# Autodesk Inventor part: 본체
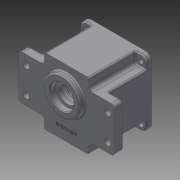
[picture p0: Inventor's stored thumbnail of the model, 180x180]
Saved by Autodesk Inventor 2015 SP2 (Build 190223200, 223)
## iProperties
Created: 2015-06
Part Number: 본체
Material: 일반
Document SubType Name: Modeling
Designer: AMC
Density: 1 g/cm^3
Appearance: 기본값
Author: AMC
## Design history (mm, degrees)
sketch "스케치4"
  geometry: L1 (-65, 30)-(65, 30); L2 (65, 30)-(65, -30); L3 (65, -30)-(-65, -30); L4 (-65, -30)-(-65, 30); 5 further points
  constraints: 8 end point, 4 midpoint, 2 horizontal alignment, 2 vertical alignment
  dimensions: "d22" = 130 distance of L2.end L3.end; "d23" = 60 distance of L1.end L2.end; "d24" = 60 distance of L3.end L1.start; "d25" = 130 distance of L1.start L1.end
extrude "돌출3" new body sketch "스케치4" distance "d26" = 12; taper "d27" = 0 deg
fillet "모깎기2" dims "d34" = 5
sketch "스케치10"
  geometry: L1 (30, -45)-(-30, -45); L2 (-30, -45)-(-30, 45); L3 (-30, 45)-(30, 45); L4 (30, 45)-(30, -45); 5 further points
  constraints: 8 end point, 4 midpoint, 2 horizontal alignment, 2 vertical alignment
  dimensions: "d57" = 60 distance of L2.end L3.end; "d58" = 90 distance of L1.end L2.end; "d59" = 60 distance of L1.start L1.end; "d60" = 90 distance of L3.end L1.start
extrude "돌출9" join sketch "스케치10" distance "d61" = 63; taper "d62" = 0 deg
sketch "스케치11"
  geometry: L1 (-30, -45)-(30, -45) reference; L2 (30, -45)-(30, 45) reference; L3 (30, 45)-(-30, 45) reference; L4 (-30, 45)-(-30, -45) reference; L5 (-45, 45)-(45, 45); L6 (45, 45)-(45, -45); L7 (45, -45)-(-45, -45); L8 (-45, -45)-(-45, 45); 5 further points
  constraints: 8 end point, 4 midpoint, 2 horizontal alignment, 2 vertical alignment
  dimensions: "d63" = 90 distance of L6.end L7.end; "d64" = 90 distance of L5.end L6.end; "d65" = 90 distance of L5.start L5.end; "d66" = 90 distance of L7.end L5.start
extrude "돌출10" join sketch "스케치11" distance "d67" = 7; taper "d68" = 0 deg
sketch "스케치12"
  geometry: L1 (-30, -45)-(-30, 45) reference; L2 (30, 45)-(30, -45) reference; L3 (30, -45)-(45, -45) reference; L4 (45, -45)-(45, 45) reference; L5 (45, 45)-(30, 45) reference; L6 (-30, 45)-(-45, 45) reference; L7 (-45, 45)-(-45, -45) reference; L8 (-45, -45)-(-30, -45) reference; C1 r 3.5 at (37, -37); C2 r 3.5 at (-37, -37); C3 r 3.5 at (-37, 37); C4 r 3.5 at (37, 37); 1 further point
  constraints: 4 centre point, 2 horizontal alignment, 2 vertical alignment
  dimensions: "d72" = 7 diameter of C1; "d73" = 7 diameter of C2; "d74" = 7 diameter of C3; "d75" = 7 diameter of C4; "d76" = 74 distance of C2.centre C1.centre; "d77" = 37 horizontal distance of point (0, 0) C1.centre; "d78" = 74 distance of C4.centre C1.centre; "d79" = 37 horizontal distance of point (0, 0) C4.centre
extrude "돌출11" cut sketch "스케치12" stored distance "d80" = 7; taper "d81" = 0 deg
sketch "스케치13"
  geometry: L1 (-60, -30)-(-30, -30) reference; L2 (65, -25)-(65, 25) reference; L3 (60, 30)-(30, 30) reference; L4 (30, 45)-(30, 30) reference; L5 (-30, 45)-(30, 45) reference; L6 (-30, -45)-(-30, -30) reference; L7 (-65, 25)-(-65, -25) reference; L8 (30, -45)-(-30, -45) reference; L9 (30, -30)-(60, -30) reference; L10 (-30, 30)-(-30, 45) reference; L11 (-30, 30)-(-60, 30) reference; L12 (30, -30)-(30, -45) reference; C1 r 4.5 at (55, -17.5); C2 r 4.5 at (-55, -17.5); C3 r 4.5 at (-55, 17.5); C4 r 4.5 at (55, 17.5); A1 r 5 centre (60, -25) between (60, -30) and (65, -25) reference; A2 r 5 centre (60, 25) between (65, 25) and (60, 30) reference; A3 r 5 centre (-60, 25) between (-60, 30) and (-65, 25) reference; A4 r 5 centre (-60, -25) between (-65, -25) and (-60, -30) reference; 1 further point
  constraints: 4 centre point, 2 horizontal alignment, 2 vertical alignment
  dimensions: "d82" = 9 diameter of C1; "d83" = 9 diameter of C2; "d84" = 9 diameter of C3; "d85" = 9 diameter of C4; "d86" = 110 distance of C1.centre C2.centre; "d87" = 55 horizontal distance of point (0, 0) C1.centre; "d88" = 35 distance of C1.centre C4.centre; "d89" = 17.5 vertical distance of C4.centre point (0, 0)
extrude "돌출12" cut sketch "스케치13" stored distance "d90" = 7; taper "d91" = 0 deg
sketch "스케치14"
  geometry: C1 r 25 at (0, -11); 1 further point
  constraints: 1 centre point, 1 vertical alignment
  dimensions: "d93" = 50 diameter of C1; "d94" = 11 distance of point (0, 0) C1.centre
extrude "돌출13" join sketch "스케치14" distance "d95" = 7; taper "d96" = 0 deg
fillet "모깎기9" dims "d97" = 2
sketch "스케치15"
  geometry: L1 (-38, 0)-(-45, 0) reference; L2 (-45, 0)-(-45, 70) reference; L3 (-45, 70)-(45, 70) reference; L4 (45, 70)-(45, 0) reference; L5 (45, 0)-(16, 0) reference; L6 (14, -2)-(14, -5) reference; L7 (12, -7)-(-34, -7) reference; L8 (-36, -5)-(-36, -2) reference; L9 (12, -7)-(-34, -7) reference; L10 (-11, -7)-(-11, 70); L11 (-11, -7)-(-27, -7); L12 (-27, -7)-(-27, 1); L13 (-27, 1)-(-23.5, 1); L14 (-23.5, 1)-(-23.5, 6); L15 (-23.5, 6)-(-28.5, 6); L16 (-28.5, 6)-(-28.5, 16); L17 (-28.5, 16)-(-11, 16); A1 r 2 centre (16, -2) between (14, -2) and (16, 0) reference; A2 r 2 centre (-38, -2) between (-38, 0) and (-36, -2) reference; A3 r 2 centre (12, -5) between (12, -7) and (14, -5) reference; A4 r 2 centre (-34, -5) between (-36, -5) and (-34, -7) reference; 1 further point
  constraints: 16 end point, 3 point on line, 1 midpoint
  dimensions: "d98" = 11 distance from line of L10 point (0, 0); "d99" = 32 diameter of L12 L10; "d100" = 25 diameter of L14 L10; "d101" = 35 diameter of L16 L10; "d102" = 8 distance of L11.end L12.end; "d103" = 10 distance of L15.end L16.end; "d104" = 5 distance of L13.end L14.end; "d105" = 23 distance between parallel lines of L17 L11; "d106" = 3.5 distance of L12.end L13.end
  node "절단 모서리 투영1"
sketch "스케치16"
  geometry: L1 (30, 45)-(30, -45) reference; L2 (45, -45)-(30, -45) reference; L3 (45, 45)-(45, -45) reference; L4 (30, 45)-(45, 45) reference; L5 (-30, 45)-(30, 45) reference; L6 (-30, -45)-(-30, 45) reference; L7 (-30, -45)-(-45, -45) reference; L8 (-45, -45)-(-45, 45) reference; L9 (-45, 45)-(-30, 45) reference; L10 (30, -45)-(-30, -45) reference; L11 (45, 45)-(45, -45) reference; L12 (-45, -45)-(-45, 45) reference; L13 (45, -30)-(-45, -30); L14 (-45, -30)-(-45, 30); L15 (-45, 30)-(45, 30); L16 (45, 30)-(45, -30); C1 r 3.5 at (37, -37) reference; C2 r 3.5 at (-37, -37) reference; C3 r 3.5 at (-37, 37) reference; C4 r 3.5 at (37, 37) reference; 4 further points
  constraints: 8 end point, 2 point on line, 1 horizontal alignment
  dimensions: "d121" = 60 distance between parallel lines of L15 L13; "d122" = 90 distance of L13.start L13.end; "d123" = 60 distance of L13.end L14.end; "d124" = 90 distance of L14.end L15.end
extrude "돌출14" join sketch "스케치16" stored distance "d125" = 7; taper "d126" = 0 deg
fillet "모깎기12" dims "d127" = 5
fillet "모깎기13" dims "d128" = 8
fillet "모깎기14" dims "d129" = 2
fillet "모깎기15" dims "d130" = 2
fillet "모깎기16" dims "d131" = 2
sketch "스케치18"
  geometry: C1 r 40 at (0, 0); 1 further point
  constraints: 1 centre point, 1 coincident
  dimensions: "d135" = 80 diameter of C1
extrude "돌출16" cut sketch "스케치18" distance "d136" = 9; taper "d137" = 0 deg
revolve "회전2" stored, may be unused: angle "d141" = 90 deg
sketch "스케치20"
  geometry: C1 r 39 at (0, 0); 1 further point
  constraints: 1 centre point, 1 coincident
  dimensions: "d142" = 78 diameter of C1
extrude "돌출18" cut sketch "스케치20" distance "d143" = 45; taper "d144" = 0 deg
sketch "스케치21"
  geometry: C1 r 11 at (0, 20); 1 further point
  constraints: 1 centre point, 1 vertical alignment
  dimensions: "d145" = 22 diameter of C1; "d146" = 20 distance of C1.centre point (0, 0)
extrude "돌출19" cut sketch "스케치21" distance "d147" = 7; taper "d148" = 0 deg
sketch "스케치22"
  geometry: L1 (-30, -65)-(-30, -55) reference; L2 (-35, -50)-(-60, -50) reference; L3 (-65, -45)-(-65, 5) reference; L4 (-60, 10)-(-35, 10) reference; L5 (-30, 15)-(-30, 25) reference; L6 (-30, 25)-(30, 25) reference; L7 (30, 25)-(30, 15) reference; L8 (35, 10)-(60, 10) reference; L9 (65, 5)-(65, -45) reference; L10 (60, -50)-(35, -50) reference; L11 (30, -55)-(30, -65) reference; L12 (30, -65)-(-30, -65) reference; C1 r 11 at (0, 0) reference; C2 r 17.5 at (0, -31) reference; C3 r 4.5 at (55, -2.5) reference; C4 r 4.5 at (-55, -37.5) reference; C5 r 4.5 at (55, -37.5) reference; C6 r 4.5 at (-55, -2.5) reference; C7 r 9.5 at (0, 0); A1 r 5 centre (-35, -55) between (-30, -55) and (-35, -50) reference; A2 r 5 centre (-60, -45) between (-65, -45) and (-60, -50) reference; A3 r 5 centre (-60, 5) between (-60, 10) and (-65, 5) reference; A4 r 5 centre (-35, 15) between (-35, 10) and (-30, 15) reference; A5 r 5 centre (35, 15) between (30, 15) and (35, 10) reference; A6 r 5 centre (60, 5) between (65, 5) and (60, 10) reference; A7 r 5 centre (60, -45) between (60, -50) and (65, -45) reference; A8 r 5 centre (35, -55) between (35, -50) and (30, -55) reference; 1 further point
  constraints: 1 centre point, 1 coincident
  dimensions: "d149" = 19 diameter of C7
extrude "돌출20" cut sketch "스케치22" distance "d150" = 1; taper "d151" = 0 deg
fillet "모깎기17" dims "d152" = 2
fillet "모깎기18" dims "d153" = 0.3
sketch "스케치23"
  geometry: L1 (0, 0)-(-24.749, -24.749); L2 (0, 0)-(35, 0); A1 r 39 centre (0, 0) between (-32.777, -21.134) and (-21.134, -32.777) reference; A2 r 35 centre (0, 0) between (-27.412, -21.762) and (-21.762, -27.412); A3 r 4 centre (-24.749, -24.749) between (-21.809, -27.462) and (-27.462, -21.809); A4 r 3.5 centre (-29.836, -19.238) between (-32.777, -21.134) and (-27.412, -21.762); A5 r 3.5 centre (-19.238, -29.836) between (-21.762, -27.412) and (-21.134, -32.777); A6 r 39 centre (0, 0) between (-32.777, -21.134) and (-21.134, -32.777); 1 further point
  constraints: 14 point on circle, 5 centre point, 4 end point, 4 tangent, 3 coincident, 1 equal length, 1 horizontal
  dimensions: "d154" = 70 diameter of A2; "d155" = 35 distance of L1.start L1.end; "d156" = 135 deg angle of L1 L2; "d157" = 8 diameter of A3; "d158" = 7 diameter of A4; "d159" = 7 diameter of A5
extrude "돌출21" join sketch "스케치23" stored distance "d161" = 1; taper "d162" = 0 deg
sketch "스케치24"
  geometry: C1 r 40 at (0, 0) reference; A1 r 39 centre (0, 0) between (-21.134, -32.777) and (-32.777, -21.134) reference; A2 r 3.5 centre (-19.238, -29.836) between (-21.809, -27.462) and (-21.134, -32.777) reference; A3 r 4 centre (-24.749, -24.749) between (-21.809, -27.462) and (-27.462, -21.809) reference; A4 r 3.5 centre (-29.836, -19.238) between (-32.777, -21.134) and (-27.462, -21.809) reference; 2 further points
  constraints: 1 coincident
hole "구멍1" sketch "스케치24" at (-24.749, -24.749) diameter "d163" = 3.242; stored, may be unused: countersink angle "d167" = 90 deg, drill point angle "d169" = 118 deg; dims "d164" = 12, "d165" = 4, "d166" = 2, "d168" = 15
sketch "스케치26"
  geometry: L1 (-30, -45)-(-30, -35) reference; L2 (-35, -30)-(-43, -30) reference; L3 (-45, -28)-(-45, 28) reference; L4 (-43, 30)-(-35, 30) reference; L5 (-30, 35)-(-30, 45) reference; L6 (-30, 45)-(30, 45) reference; L7 (30, 45)-(30, 35) reference; L8 (35, 30)-(43, 30) reference; L9 (45, 28)-(45, -28) reference; L10 (43, -30)-(35, -30) reference; L11 (30, -35)-(30, -45) reference; L12 (30, -45)-(-30, -45) reference; C1 r 11 at (0, 20) reference; C2 r 17.5 at (0, -11) reference; C3 r 39 at (0, 0); A1 r 3.5 centre (-19.238, 29.836) between (-21.134, 32.777) and (-21.809, 27.462) reference; A2 r 4 centre (-24.749, 24.749) between (-27.462, 21.809) and (-21.809, 27.462) reference; A3 r 3.5 centre (-29.836, 19.238) between (-27.462, 21.809) and (-32.777, 21.134) reference; A4 r 39 centre (0, 0) between (-32.777, 21.134) and (-32.777, -21.134) reference; A5 r 3.5 centre (-29.836, -19.238) between (-32.777, -21.134) and (-27.462, -21.809) reference; A6 r 4 centre (-24.749, -24.749) between (-21.809, -27.462) and (-27.462, -21.809) reference; A7 r 3.5 centre (-19.238, -29.836) between (-21.809, -27.462) and (-21.134, -32.777) reference; A8 r 39 centre (0, 0) between (-21.134, -32.777) and (21.134, -32.777) reference; A9 r 3.5 centre (19.238, -29.836) between (21.134, -32.777) and (21.809, -27.462) reference; A10 r 4 centre (24.749, -24.749) between (27.462, -21.809) and (21.809, -27.462) reference; A11 r 3.5 centre (29.836, -19.238) between (27.462, -21.809) and (32.777, -21.134) reference; A12 r 39 centre (0, 0) between (32.777, -21.134) and (32.777, 21.134) reference; A13 r 3.5 centre (29.836, 19.238) between (32.777, 21.134) and (27.462, 21.809) reference; A14 r 4 centre (24.749, 24.749) between (21.809, 27.462) and (27.462, 21.809) reference; A15 r 3.5 centre (19.238, 29.836) between (21.809, 27.462) and (21.134, 32.777) reference; A16 r 39 centre (0, 0) between (21.134, 32.777) and (-21.134, 32.777) reference; A17 r 5 centre (-35, -35) between (-30, -35) and (-35, -30) reference; A18 r 2 centre (-43, -28) between (-45, -28) and (-43, -30) reference; A19 r 2 centre (-43, 28) between (-43, 30) and (-45, 28) reference; A20 r 5 centre (-35, 35) between (-35, 30) and (-30, 35) reference; A21 r 5 centre (35, 35) between (30, 35) and (35, 30) reference; A22 r 2 centre (43, 28) between (45, 28) and (43, 30) reference; A23 r 2 centre (43, -28) between (43, -30) and (45, -28) reference; A24 r 5 centre (35, -35) between (35, -30) and (30, -35) reference; A25 r 20.5 centre (0, -11) between (-7.402, 8.117) and (7.402, 8.117); A26 r 14 centre (0, 20) between (7.402, 8.117) and (-7.402, 8.117); 1 further point
  constraints: 4 point on circle, 3 centre point, 3 coincident
  dimensions: "d175" = 41 diameter of A25; "d176" = 78 diameter of C3; "d177" = 28 diameter of A26
extrude "돌출23" cut sketch "스케치26" distance "d178" = 7; taper "d179" = 0 deg
fillet "모깎기19" dims "d180" = 3
sketch "스케치27"
  geometry: L1 (30, -35)-(30, -43) reference; L2 (30, -43)-(30, -45) reference; L3 (30, -45)-(-30, -45) reference; L4 (-30, -45)-(-30, -43) reference; L5 (-30, -43)-(-30, -35) reference; L6 (-35, -30)-(-43, -30) reference; L7 (-45, -28)-(-45, 28) reference; L8 (-43, 30)-(-35, 30) reference; L9 (-30, 35)-(-30, 43) reference; L10 (-30, 43)-(-30, 45) reference; L11 (-30, 45)-(30, 45) reference; L12 (30, 45)-(30, 43) reference; L13 (30, 43)-(30, 35) reference; L14 (35, 30)-(43, 30) reference; L15 (45, 28)-(45, -28) reference; L16 (43, -30)-(35, -30) reference; C1 r 1.621 at (24.749, -24.749) reference; C2 r 1.621 at (24.749, 24.749) reference; C3 r 1.621 at (-24.749, 24.749) reference; C4 r 1.621 at (-24.749, -24.749) reference; C5 r 40 at (0, 0) reference; A1 r 39 centre (0, 0) between (32.777, -21.134) and (32.777, 21.134) reference; A2 r 3.5 centre (29.836, 19.238) between (32.777, 21.134) and (27.462, 21.809) reference; A3 r 4 centre (24.749, 24.749) between (21.809, 27.462) and (27.462, 21.809) reference; A4 r 3.5 centre (19.238, 29.836) between (21.809, 27.462) and (21.134, 32.777) reference; A5 r 39 centre (0, 0) between (21.134, 32.777) and (-21.134, 32.777) reference; A6 r 3.5 centre (-19.238, 29.836) between (-21.134, 32.777) and (-21.809, 27.462) reference; A7 r 4 centre (-24.749, 24.749) between (-27.462, 21.809) and (-21.809, 27.462) reference; A8 r 3.5 centre (-29.836, 19.238) between (-27.462, 21.809) and (-32.777, 21.134) reference; A9 r 39 centre (0, 0) between (-32.777, 21.134) and (-32.777, -21.134) reference; A10 r 3.5 centre (-29.836, -19.238) between (-32.777, -21.134) and (-27.462, -21.809) reference; A11 r 4 centre (-24.749, -24.749) between (-21.809, -27.462) and (-27.462, -21.809) reference; A12 r 3.5 centre (-19.238, -29.836) between (-21.809, -27.462) and (-21.134, -32.777) reference; A13 r 39 centre (0, 0) between (-21.134, -32.777) and (21.134, -32.777) reference; A14 r 3.5 centre (19.238, -29.836) between (21.134, -32.777) and (21.809, -27.462) reference; A15 r 4 centre (24.749, -24.749) between (27.462, -21.809) and (21.809, -27.462) reference; A16 r 3.5 centre (29.836, -19.238) between (27.462, -21.809) and (32.777, -21.134) reference; A17 r 5 centre (-35, -35) between (-30, -35) and (-35, -30) reference; A18 r 2 centre (-43, -28) between (-45, -28) and (-43, -30) reference; A19 r 2 centre (-43, 28) between (-43, 30) and (-45, 28) reference; A20 r 5 centre (-35, 35) between (-35, 30) and (-30, 35) reference; A21 r 5 centre (35, 35) between (30, 35) and (35, 30) reference; A22 r 2 centre (43, 28) between (45, 28) and (43, 30) reference; A23 r 2 centre (43, -28) between (43, -30) and (45, -28) reference; A24 r 5 centre (35, -35) between (35, -30) and (30, -35) reference; 1 further point
extrude "돌출24" join sketch "스케치27" stored distance "d181" = 7; taper "d182" = 0 deg
chamfer "모따기2" distance "d183" = 1; stored, may be unused: second distance "d184" = 2, angle "d185" = 45 deg
fillet "모깎기20" dims "d186" = 2
fillet "모깎기21" dims "d187" = 2
fillet "모깎기22" dims "d188" = 0.3
sketch "스케치28"
  geometry: L1 (-30, 45)-(30, 45) reference; 2 further points
  constraints: 1 vertical alignment, 1 other
  dimensions: "d189" = 15 distance from line of L1 point (0, 30)
feature "엠보싱1" sketch "스케치28" dims "d62" = 0, "d190" = 0.5, "d191" = 0
fillet "모깎기23" dims "d192" = 2
fillet "모깎기24" dims "d193" = 2
node "솔리드2"
pattern_circular "원형 패턴1" dims angle "d171" = 360 deg
node "투영된 루프10"
node "투영된 루프11"
node "투영된 루프12"
node "투영된 루프13"
node "투영된 루프14"
node "절단 모서리 투영2"
node "절단 모서리 투영3"
node "절단 모서리 투영4"
node "절단 모서리 투영5"
